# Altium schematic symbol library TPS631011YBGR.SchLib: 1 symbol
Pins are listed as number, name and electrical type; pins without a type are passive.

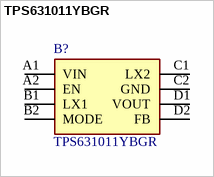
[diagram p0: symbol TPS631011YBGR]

## TPS631011YBGR
designator B?
Switching Voltage Regulators 1.5-A output current buck-boost converter 8-DSBGA -40 to 125; Manufacturer_Name: Texas Instruments; Geometry.Height: 0.5mm
footprint BGA8C40P2X4_86X176X50
pins: A1 VIN, A2 EN, B1 LX1, B2 MODE, C1 LX2, C2 GND, D1 VOUT, D2 FB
